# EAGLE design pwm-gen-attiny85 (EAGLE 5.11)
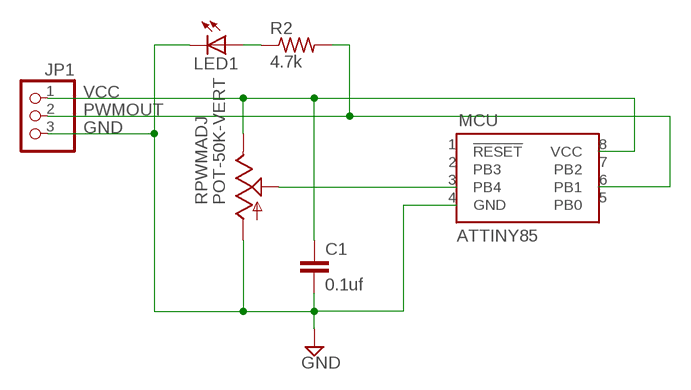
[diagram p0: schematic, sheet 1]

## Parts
C1  0.1uf  C-EUC0805  [C0805]
JP1  PINHD-1X3  [1X03]
LED1  LED5MM  [LED5MM]
MCU  ATTINY85  [8DIP]
R2  4.7k  R-US_R1206  [R1206]
RPWMADJ  POT-50K-VERT  POT-TRIM-0.35IN  [POT-TRIM-0.35IN]

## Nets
GND: C1.2 JP1.3 LED1.K(C) MCU.4(GND) RPWMADJ.1(A)
N$1: MCU.3(PB4) RPWMADJ.2(S)
N$4: LED1.A R2.1
PWMOUT: JP1.2 MCU.6(PB1) R2.2
VCC: C1.1 JP1.1 MCU.8(VCC) RPWMADJ.3(E)
Unconnected: MCU.1(!RESET) MCU.2(PB3) MCU.5(PB0) MCU.7(PB2)

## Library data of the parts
C1 = resistor:C-EU: CAPACITOR, European symbol
JP1 = pinhead:PINHD-1X3: PIN HEADER
LED1 = led:LED: LED
MCU = trl:ATTINY85
R2 = resistor:R-US_: RESISTOR, American symbol
RPWMADJ = trl:POT-TRIM-0.35IN

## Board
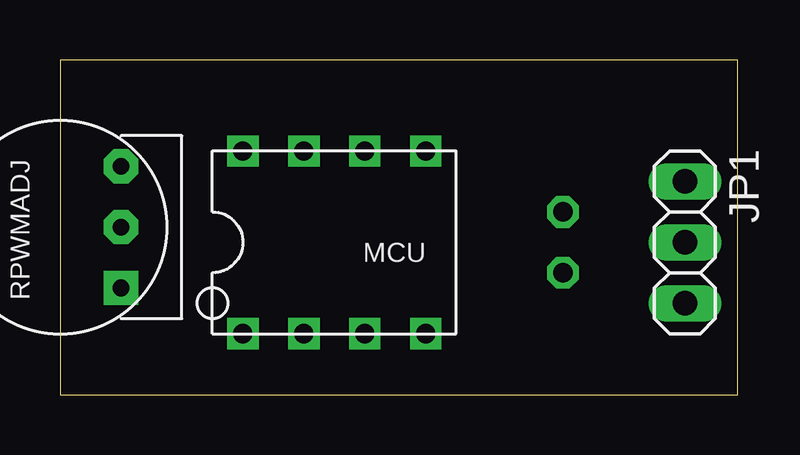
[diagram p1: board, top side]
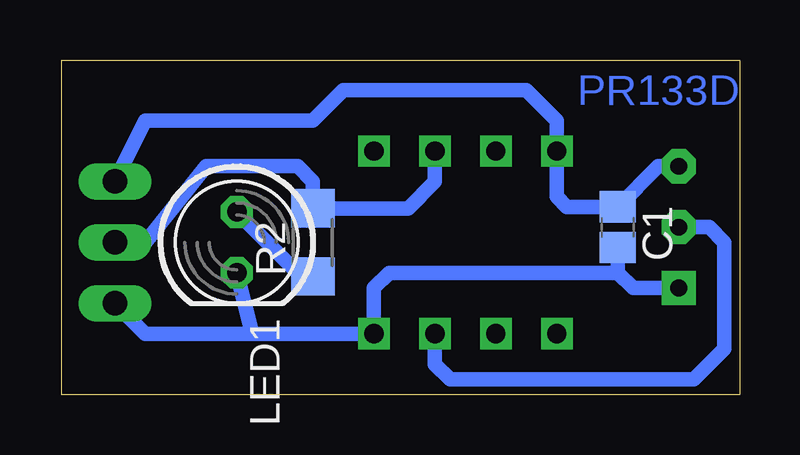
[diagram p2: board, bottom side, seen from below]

Size 28.25 x 13.96 mm. Coordinates in mm from the lower left corner, seen from the top.
Outline: 0,0 28.25,0 28.25,13.96 0,13.96 0,0
Copper layers (1*16): Top 0.035mm / dielectric 1.5mm / Bottom 0.035mm
Design rules "default": minimum track width 10mil, minimum drill 24mil, track to track 8mil, track to pad 8mil, pad to pad 8mil, via to via 8mil, smd to smd 8mil, copper to edge 40mil, drill to drill 8mil, minimum pad ring 10mil, minimum via ring 8mil, stop-mask expansion 4mil, vias tented up to drill 0mil, thermal gap 10mil

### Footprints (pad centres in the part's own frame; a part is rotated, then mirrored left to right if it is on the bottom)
C0805 = smd 1.3 x 1.5: 1 -0.85,0; 2 0.85,0
1X03 = drill 1.016 long: 1 -2.54,0; 2 0,0; 3 2.54,0
LED5MM = drill 0.813 octagon: A -1.27,0; K 1.27,0
8DIP = drill 0.8 square: 1 -3.81,3.81; 2 -3.81,1.27; 3 -3.81,-1.27; 4 -3.81,-3.81; 5 3.81,-3.81; 6 3.81,-1.27; 7 3.81,1.27; 8 3.81,3.81
R1206 = smd 1.6 x 1.803: 1 -1.422,0; 2 1.422,0
POT-TRIM-0.35IN = drill 0.7 pad 1.422 square: 1 -2.54,-3.81 | drill 0.7 pad 1.422 octagon: 2 0,-3.81; 3 2.54,-3.81

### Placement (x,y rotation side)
C1  5.08,6.99 270 bottom
JP1  26.04,6.35 270 top
LED1  20.95,6.35 270 bottom
MCU  11.43,6.35 90 top
R2  17.78,6.35 90 bottom
RPWMADJ  -1.27,6.99 90 top

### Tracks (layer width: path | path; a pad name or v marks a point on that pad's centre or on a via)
GND
  Bottom 0.61: RPWMADJ.1 4.45,4.45 5.08,5.08 | 5.08,5.08 C1.2 | 5.08,5.08 14.61,5.08 15.24,4.45 MCU.4 20.32,2.54 | 20.32,2.54 LED1.K | 20.32,2.54 24.77,2.54 JP1.3
N$1
  Bottom 0.61: RPWMADJ.2 1.27,6.99 0.64,6.35 0.64,1.91 1.91,0.64 12.06,0.64 12.7,1.27 MCU.3
N$4
  Bottom 0.61: R2.1 18.26,4.93 LED1.A
PWMOUT
  Bottom 0.61: JP1.2 24.77,6.35 22.23,9.53 18.41,9.53 17.78,8.89 R2.2 13.82,7.77 12.7,8.89 MCU.6
VCC
  Bottom 0.61: RPWMADJ.3 3.39,9.53 C1.1 7.2,7.83 7.62,8.26 MCU.8 7.62,11.43 8.89,12.7 16.51,12.7 17.78,11.43 24.77,11.43 JP1.1

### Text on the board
Bottom: PR133D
